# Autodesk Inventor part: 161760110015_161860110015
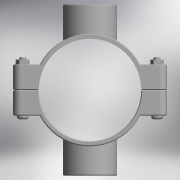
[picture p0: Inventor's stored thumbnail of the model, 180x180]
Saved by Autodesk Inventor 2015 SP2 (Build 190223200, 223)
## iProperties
Created: 2017-05
Part Number: 161760110015_161860110015
Material: Generic
Description: PLASSON DOUBLE SADDLE 110-1.1/2"
Document SubType Name: Modeling
Designer: KIM
Density: 1 g/cm^3
Appearance: Default
Author: KIM
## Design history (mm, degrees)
derived "16176.ipt"
feature "Solid1::16176.ipt"
feature "Solid2::16176.ipt"
tag "TaggingFeature1"
body "Solid1"
body "Solid2"
other parameters: "d0" = 121, "d1" = 165, "d2" = 55, "d4" = 116, "d5" = 0, "d6" = 8.25, "d7" = 165, "d8" = 0.1, "d10" = 0, "d11" = 1.1, "d20" = 1.1, "d23" = 1.1, "d36" = 13, "d37" = 10.4, "d38" = 63, "d39" = 0, "d40" = 3, "d41" = 5, "d42" = 0, "d43" = 8, "d44" = 3, "d45" = 0, "d46" = 1.1, "d52" = 44.845, "d53" = 25, "d54" = 0, "d57" = 0, "d58" = 118.8, "d60" = 0, "d62" = 13, "d63" = 10.4, "d66" = 95.2, "d67" = 184, "d68" = 58.2985, "d69" = 44.845, "d70" = 25, "d71" = 0, "d74" = 0, "d75" = 1.1, "G_" = 44.845, "A_" = 92, "L_" = 165, "L_1" = 116, "l_2" = 25
